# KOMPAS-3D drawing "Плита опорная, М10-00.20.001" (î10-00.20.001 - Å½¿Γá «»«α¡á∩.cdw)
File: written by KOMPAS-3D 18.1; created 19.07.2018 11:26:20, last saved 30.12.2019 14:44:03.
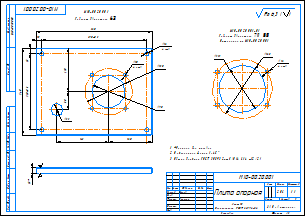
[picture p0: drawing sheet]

Sheet 1: A3, landscape

Document properties: Организация: Мирончук; Полное имя файла: C:\Users\User\Desktop\Магна 10 для Караби\М10-00.20.001 - Плита опорная.cdw; Масса: 2.06; Параметр неуказанной шероховатости: Ra 6,3

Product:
- Part/product: Плита опорная  | designation М10-00.20.001
    Масса: 2.06392
    Раздел спецификации: Детали
    Форматы листов документа: A3
- Part/product: Плита опорная  | designation М10-00.20.001-01
    Масса: 1.84628
    Раздел спецификации: Детали
    Форматы листов документа: A3

Title block, sheet 1: Наименование: Плита опорная; designation: М10-00.20.001; Масса: 2,06; scale: 1:1; Количество листов документа: 1; organisation: ЗАО «Астерион»; Форматы листов документа: A3; stored path: Z:\Магна\Магна Ins\Магна ins 10\М10-00.00.000\3Д\М10-00.20.001 - Плита опорная.cdw; Разработал: Милов; Т. контр.: Лучихин

Views: Вид 1, Спереди, Проекционный вид 2
Referenced files in Z:\Магна\Магна Ins\Магна ins 10\М10-00.00.000\3Д\: М10-00.20.001 - Плита опорная.m3d
Referenced files in C:\Users\User\Desktop\Магна 10 для Караби\: М10-00.20.001 - Плита опорная.m3d
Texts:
  Лист 15
  Полипропилен  ГОСТ 26996-86
  Габарит двигателя 63
  Габарит двигателя 71, 80
  Остальное см. М10-00.20.001
  Ra 6,3
  Ra 6,3 ( )
Dimensions and other numbers on the sheet: 290±0,3; 320; 210±0,3; 240; 130; 90; 50; 143; 33; 120; 15; 10; 4 отв.; 12; 131; 165; 1:1; 1; 2,06

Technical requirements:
  *Размеры для справок.
  Неуказанные фаски 1х45 .
  Общие допуски ГОСТ 30893.2-mK (H14, h14,  t2/2).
